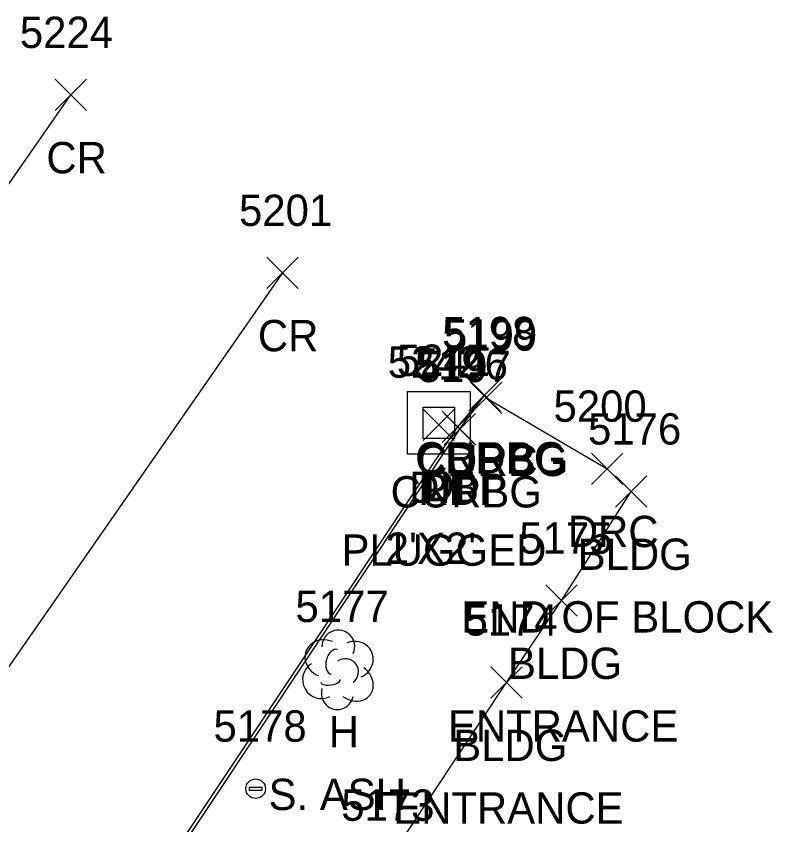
# Model space of a CAD drawing. Extents: x 1618146 to 1620418, y 640749 to 641927.
# Drawn here: x 1620369.4 to 1620417.7, y 641036.5 to 641088.1 of the extents above; entities that cross this region are included whole.
import ezdxf

# ---------------------------------------------------------------- set-up
doc = ezdxf.new("R2010")
doc.units = 0
for name, color, linetype in [('D_A', 7, 'Continuous'), ('D_C', 7, 'Continuous'), ('D_I', 7, 'Continuous'), ('D_TIC', 7, 'Continuous'), ('DS', 7, 'Continuous'), ('L_A', 7, 'Continuous'), ('L_C', 7, 'Continuous'), ('L_I', 7, 'Continuous'), ('L_TIC', 7, 'Continuous'), ('LBC', 7, 'Continuous'), ('LTD', 7, 'Continuous'), ('P_A', 7, 'Continuous'), ('P_I', 7, 'Continuous'), ('P_TIC', 7, 'Continuous'), ('PET', 7, 'Continuous'), ('PRC', 7, 'Continuous'), ('R_A', 7, 'Continuous'), ('R_I', 7, 'Continuous'), ('R_TIC', 7, 'Continuous'), ('RC', 7, 'Continuous'), ('RDP', 7, 'Continuous'), ('S_I', 7, 'Continuous'), ('SPM', 7, 'Continuous')]:
    doc.layers.add(name, color=color, linetype=linetype)

msp = doc.modelspace()

# ---------------------------------------------------------------- linework, layer by layer
at = {"layer": 'D_TIC'}
for points in [[(1620395.386, 641061.017), (1620397.386, 641063.017)], [(1620397.386, 641061.017), (1620395.386, 641063.017)]]:
    msp.add_lwpolyline(points, dxfattribs=at)
at = {"layer": 'DS'}
for p, q in [((1620394.391, 641064.135), (1620398.391, 641064.135)), ((1620394.391, 641060.135), (1620394.391, 641064.135)), ((1620398.391, 641064.135), (1620398.391, 641060.135)), ((1620395.391, 641061.135), (1620395.391, 641063.135)), ((1620395.391, 641063.135), (1620397.391, 641063.135)), ((1620397.391, 641063.135), (1620397.391, 641061.135)), ((1620396.397, 641062.136), (1620396.397, 641062.136)), ((1620396.397, 641062.136), (1620396.397, 641062.136)), ((1620397.391, 641061.135), (1620395.391, 641061.135)), ((1620398.391, 641060.135), (1620394.391, 641060.135))]:
    msp.add_line(p, q, dxfattribs=at)
at = {"layer": 'L_TIC'}
for points in [[(1620407.659, 641056.754), (1620409.659, 641058.754)], [(1620409.659, 641056.754), (1620407.659, 641058.754)], [(1620403.212, 641049.791), (1620405.212, 641051.791)], [(1620405.212, 641049.791), (1620403.212, 641051.791)], [(1620399.716, 641044.556), (1620401.716, 641046.556)], [(1620401.716, 641044.556), (1620399.716, 641046.556)]]:
    msp.add_lwpolyline(points, dxfattribs=at)
at = {"layer": 'LBC'}
msp.add_lwpolyline([(1620408.483, 640968.324), (1620405.938, 640970.699), (1620404.938, 640971.606), (1620401.431, 640975.628), (1620374.928, 641002.908), (1620373.231, 641004.048), (1620377.733, 641011.253), (1620381.082, 641016.376), (1620389.179, 641028.231), (1620392.855, 641033.737), (1620400.716, 641045.556), (1620404.212, 641050.791), (1620408.659, 641057.754)], dxfattribs=at)
at = {"layer": 'LTD'}
msp.add_line((1620389.928, 641046.423), (1620389.928, 641046.423), dxfattribs=at)
msp.add_line((1620389.928, 641046.423), (1620389.928, 641046.423), dxfattribs=at)
msp.add_arc((1620389.975, 641047.857), 1.047, 335.5272, 180.9563, dxfattribs=at)
for centre, major_axis, ratio, start_param, end_param in [((1620389.136, 641047.089), (1.21, -0.512), 0.895232, 1.570796, 4.712389), ((1620390.969, 641047.006), (-1.141, -0.483), 0.949671, 1.570796, 4.712389), ((1620389.72, 641046.881), (-0.208, -0.792), 0.645439, 3.141593, 6.283185), ((1620390.428, 641046.256), (-0.5, 0.667), 0.989748, 3.141593, 6.283185), ((1620388.845, 641045.714), (0.584, -1.042), 0.959034, 3.141593, 6.283185), ((1620390.928, 641045.59), (-1.09, 0.792), 0.841452, 1.570796, 4.712389), ((1620389.47, 641045.673), (-0.625, -0.083), 0.423636, 0, 3.141593), ((1620389.928, 641044.923), (0.265, 1.061), 0.942809, 1.570796, 4.712389)]:
    msp.add_ellipse(centre, major_axis=major_axis, ratio=ratio, start_param=start_param, end_param=end_param, dxfattribs=at)
at = {"layer": 'P_TIC'}
for points in [[(1620371.9, 641082.065), (1620373.9, 641084.065)], [(1620373.9, 641082.065), (1620371.9, 641084.065)], [(1620385.404, 641070.706), (1620387.404, 641072.706)], [(1620387.404, 641070.706), (1620385.404, 641072.706)], [(1620398.294, 641062.904), (1620400.294, 641064.904)], [(1620400.294, 641062.904), (1620398.294, 641064.904)], [(1620396.595, 641060.893), (1620398.595, 641062.893)], [(1620398.595, 641060.893), (1620396.595, 641062.893)]]:
    msp.add_lwpolyline(points, dxfattribs=at)
at = {"layer": 'PET'}
msp.add_lwpolyline([(1620301.599, 640941.889), (1620306.673, 640947.652), (1620308.049, 640949.035), (1620313.723, 640955.551), (1620317.973, 640960.228), (1620327.197, 640970.287), (1620342.84, 640987.934), (1620349.43, 640995.592), (1620362.743, 641013.622), (1620363.905, 641016.91), (1620366.737, 641021.043), (1620371.936, 641023.376), (1620397.595, 641061.893), (1620399.294, 641063.904)], dxfattribs=at)
at = {"layer": 'PRC'}
for points in [[(1620224.798, 640884.187), (1620252.423, 640919.672), (1620271.906, 640945.144), (1620290.437, 640967.965), (1620293.935, 640972.261), (1620320.636, 641007.736), (1620341.521, 641037.703), (1620358.234, 641062.028), (1620372.9, 641083.065)], [(1620386.404, 641071.706), (1620361.021, 641035.235), (1620336.241, 641002.906), (1620316.225, 640977.168), (1620300.323, 640960.311), (1620296.609, 640956.784), (1620272.862, 640927.85), (1620252.181, 640901.579), (1620233.904, 640877.595)]]:
    msp.add_lwpolyline(points, dxfattribs=at)
at = {"layer": 'R_TIC'}
for points in [[(1620398.294, 641062.904), (1620400.294, 641064.904)], [(1620400.294, 641062.904), (1620398.294, 641064.904)], [(1620398.417, 641062.74), (1620400.417, 641064.74)], [(1620400.417, 641062.74), (1620398.417, 641064.74)], [(1620398.417, 641062.74), (1620400.417, 641064.74)], [(1620400.417, 641062.74), (1620398.417, 641064.74)], [(1620396.728, 641060.738), (1620398.728, 641062.738)], [(1620398.728, 641060.738), (1620396.728, 641062.738)], [(1620406.132, 641058.207), (1620408.132, 641060.207)], [(1620408.132, 641058.207), (1620406.132, 641060.207)]]:
    msp.add_lwpolyline(points, dxfattribs=at)
at = {"layer": 'RC'}
msp.add_lwpolyline([(1620362.723, 641009.972), (1620362.324, 641009.944), (1620362.823, 641013.674), (1620364.001, 641016.854), (1620366.832, 641020.747), (1620372.106, 641023.223), (1620397.728, 641061.738), (1620399.294, 641063.904), (1620399.417, 641063.74)], dxfattribs=at)
at = {"layer": 'RDP'}
msp.add_lwpolyline([(1620399.417, 641063.74), (1620407.132, 641059.207)], dxfattribs=at)
at = {"layer": 'SPM'}
msp.add_lwpolyline([(1620384.278, 641038.703), (1620385.112, 641038.703), (1620385.112, 641038.869), (1620384.278, 641038.869)], close=True, dxfattribs=at)
msp.add_circle((1620384.695, 641038.786), 0.625, dxfattribs=at)

# ---------------------------------------------------------------- texts
at = {"layer": 'D_A'}
for s, p in [('DIB', (1620394.489, 641057.017)), ('DI', (1620395.452, 641057.136))]:
    msp.add_text(s, height=2, dxfattribs=at).set_placement(p)
at = {"layer": 'D_C'}
for s, p in [('PLUGGED', (1620390.174, 641053.017)), ("2'X2'", (1620392.995, 641053.136))]:
    msp.add_text(s, height=2, dxfattribs=at).set_placement(p)
at = {"layer": 'D_I'}
for s, p in [('5242', (1620393.126, 641065.017)), ('5241', (1620393.704, 641065.136))]:
    msp.add_text(s, height=2, dxfattribs=at).set_placement(p)
at = {"layer": 'L_A'}
for s, p in [('BLDG', (1620405.25, 641052.754)), ('BLDG', (1620400.803, 641045.791)), ('H', (1620389.361, 641041.423)), ('BLDG', (1620397.307, 641040.556))]:
    msp.add_text(s, height=2, dxfattribs=at).set_placement(p)
at = {"layer": 'L_C'}
for s, p in [('END OF BLOCK', (1620397.825, 641048.754)), ('ENTRANCE', (1620396.968, 641041.791)), ('S. ASH', (1620385.519, 641037.423)), ('ENTRANCE', (1620393.472, 641036.556))]:
    msp.add_text(s, height=2, dxfattribs=at).set_placement(p)
at = {"layer": 'L_I'}
for s, p in [('5176', (1620405.911, 641060.754)), ('5175', (1620401.52, 641053.791)), ('5177', (1620387.235, 641049.423)), ('5174', (1620398.023, 641048.556)), ('5173', (1620390.162, 641036.737))]:
    msp.add_text(s, height=2, dxfattribs=at).set_placement(p)
at = {"layer": 'P_A'}
for s, p in [('CR', (1620371.333, 641078.065)), ('CR', (1620384.837, 641066.706)), ('RDP', (1620396.783, 641058.904)), ('RDP', (1620395.083, 641056.893))]:
    msp.add_text(s, height=2, dxfattribs=at).set_placement(p)
at = {"layer": 'P_I'}
for s, p in [('5224', (1620369.64, 641086.065)), ('5201', (1620383.632, 641074.706)), ('5198', (1620396.602, 641066.904)), ('5196', (1620394.847, 641064.893))]:
    msp.add_text(s, height=2, dxfattribs=at).set_placement(p)
at = {"layer": 'R_A'}
for s, p in [('CURBG', (1620394.877, 641058.904)), ('CURBG', (1620395, 641058.74)), ('DRC', (1620396.905, 641058.74)), ('CURBG', (1620393.31, 641056.738)), ('DRC', (1620404.62, 641054.207))]:
    msp.add_text(s, height=2, dxfattribs=at).set_placement(p)
at = {"layer": 'R_I'}
for s, p in [('5198', (1620396.602, 641066.904)), ('5199', (1620396.716, 641066.74)), ('5199', (1620396.716, 641066.74)), ('5197', (1620395.035, 641064.738)), ('5200', (1620403.707, 641062.207))]:
    msp.add_text(s, height=2, dxfattribs=at).set_placement(p)
at = {"layer": 'S_I'}
msp.add_text('5178', height=2, dxfattribs=at).set_placement((1620382.002, 641041.786))

doc.saveas('drawing.dxf')
